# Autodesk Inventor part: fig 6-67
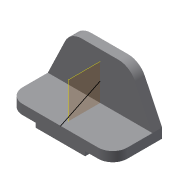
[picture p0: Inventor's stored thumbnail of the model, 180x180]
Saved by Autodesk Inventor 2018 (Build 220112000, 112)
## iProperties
Shininess: 77.0
Length Units: 11269
Angle Units: 11279
Time Units: 11290
Mass Units: 11283
Length Display Precision: 3
Angle Display Precision: 2
Created: 2001-12
Part Number: fig 6-67
Document SubType Name: Modeling
Designer: Renu Muthoo
Density: 1 g/cm^3
Material: Generic
Appearance: Default
Density: 0.0
Volumn: 0.0
Area: 0.0
PropertySet Name: Model Information
Control State: 0
Master: False
Checked Out: False
Author: Renu Muthoo
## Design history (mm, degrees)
node "Sketch1"
sketch "Sketch2"
  geometry: L1 (-67.219, 19.116)-(148.781, 19.116); L2 (148.781, 19.116)-(148.781, -0.884); L3 (-67.219, -0.884)-(-67.219, 19.116); L4 (-10.219, -0.884)-(-10.219, -9.884); L5 (-10.219, -9.884)-(91.781, -9.884); L6 (91.781, -9.884)-(91.781, -0.884); L7 (148.781, -0.884)-(91.781, -0.884); L8 (-10.219, -0.884)-(-67.219, -0.884)
  constraints: 16 end point, 5 parallel, 4 perpendicular, 2 equal length, 1 horizontal
  dimensions: "d0" = 102 distance of L4.end L5.end; "d1" = 57 distance of L4.start L3.start; "d2" = 29 distance between parallel lines of L1 L5; "d3" = 20 distance of L1.end L2.end
extrude "Extrusion1" new body sketch "Sketch2" distance "d4" = 102; taper "d5" = 0 deg
sketch "Sketch3"
  geometry: L1 (67.219, -19.116)-(-148.781, -19.116) reference; L2 (67.219, -19.116)-(31.475, -93.564); L3 (-2.781, -115.116)-(-78.781, -115.116); L4 (-113.038, -93.564)-(-148.781, -19.116); A1 r 38 centre (-2.781, -77.116) between (-2.781, -115.116) and (31.475, -93.564); A2 r 38 centre (-78.781, -77.116) between (-113.038, -93.564) and (-78.781, -115.116)
  constraints: 6 end point, 4 point on circle, 4 tangent, 2 centre point, 1 equal length, 1 equal radius, 1 parallel
  dimensions: "d6" = 96 distance between parallel lines of L3 L1; "d7" = 38 radius of A1; "d8" = 76 distance of A2.centre A1.centre
extrude "Extrusion2" join sketch "Sketch3" distance "d9" = 20; taper "d10" = 0 deg
fillet "Fillet1" dims "d11" = 30
workplane "Work Plane1"
sketch "Sketch7"
  geometry: L1 (0, -82)-(-39.557, 0)
  constraints: 2 end point
body "Solid1"
other parameters: "d12" = -108
